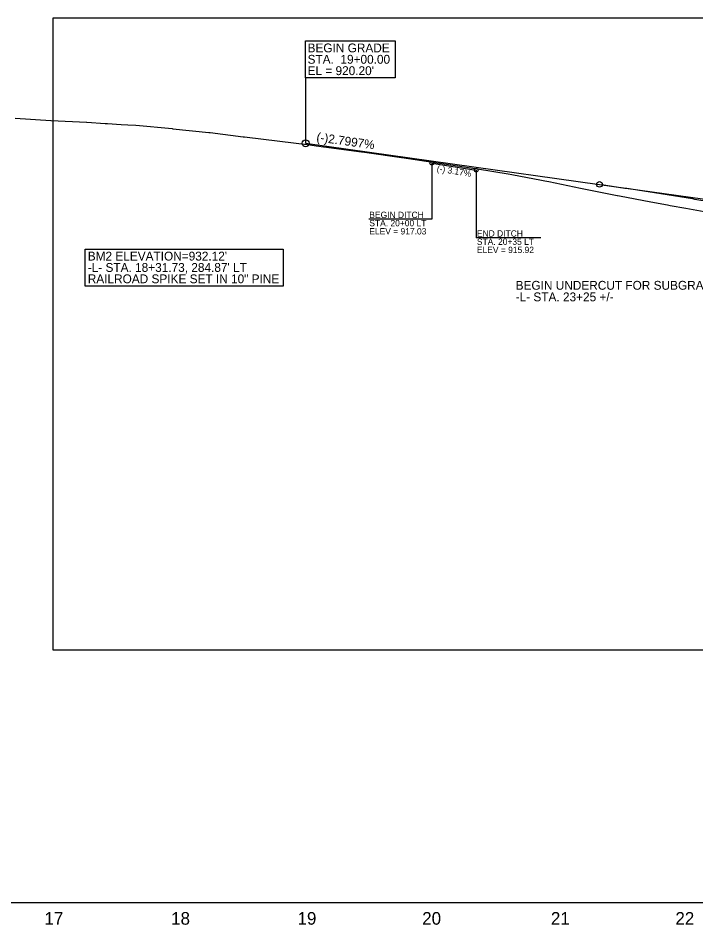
# Model space of a CAD drawing. Extents: x 1968019 to 1983409, y 545058 to 567558.
# Drawn here: x 1969515 to 1970052, y 566291 to 567008 of the extents above; entities that cross this region are included whole.
import ezdxf

# ---------------------------------------------------------------- set-up
doc = ezdxf.new("R2010")
doc.units = 0
for name, color, linetype in [('Exist Profile Cell', 7, 'Continuous'), ('Exist Vertical Profile Ground Line', 7, 'Continuous'), ('Exist Vertical Profile Horizontal Axis Label Major', 7, 'Continuous'), ('Prop Grid Mask', 7, 'Continuous'), ('Prop Road Sect_ Recs - UC (Tx)', 7, 'Continuous'), ('Prop Vertical Profile Curve Label', 7, 'Continuous'), ('Prop Vertical Profile Ditch Grade Left', 7, 'Continuous'), ('Prop Vertical Profile Ditch Grade Left Label', 7, 'Continuous'), ('Prop Vertical Profile Grade', 7, 'Continuous'), ('Prop Vertical Profile Grade Label', 7, 'Continuous'), ('Prop VPI Label', 7, 'Continuous'), ('Scratch_Level_8', 7, 'Continuous')]:
    doc.layers.add(name, color=color, linetype=linetype)

msp = doc.modelspace()

# ---------------------------------------------------------------- linework, layer by layer
at = {"layer": 'Exist Profile Cell'}
msp.add_line((1968842.96, 566308.43), (1972642.96, 566308.43), dxfattribs=at)
at = {"layer": 'Exist Vertical Profile Ground Line'}
for points in [[(1969513.03, 566929.29), (1969541.49, 566927.51), (1969541.53, 566927.51), (1969569.71, 566926.02), (1969569.88, 566926.01), (1969584.49, 566925.1), (1969584.5, 566925.1), (1969586.18, 566924.99), (1969597, 566924.28), (1969597.08, 566924.28), (1969602.31, 566924), (1969608.52, 566923.65), (1969608.62, 566923.65), (1969637.31, 566920.95), (1969638.03, 566920.89), (1969666.44, 566917.96), (1969666.98, 566917.9), (1969667.48, 566917.84), (1969693.64, 566914.53), (1969694.34, 566914.42), (1969694.67, 566914.38), (1969722.64, 566911.07), (1969722.72, 566911.06), (1969746.25, 566908.11), (1969751.44, 566907.46), (1969751.68, 566907.43), (1969757.3, 566906.68), (1969757.49, 566906.66), (1969787.15, 566902.74), (1969787.34, 566902.71), (1969788.86, 566902.49), (1969789.66, 566902.37), (1969818.88, 566898.11)], [(1969818.88, 566898.11), (1969819.01, 566898.09), (1969819.12, 566898.07), (1969849.09, 566893.57), (1969849.11, 566893.57), (1969849.17, 566893.56), (1969877.19, 566889.52), (1969879.16, 566889.2), (1969903.24, 566885.11), (1969906.31, 566884.63), (1969929.59, 566880.26), (1969932.47, 566879.73), (1969935.5, 566879.12), (1969960.47, 566873.97), (1969989.61, 566868.13), (1969989.78, 566868.1), (1969989.84, 566868.08), (1969991.42, 566867.78), (1970016.15, 566862.98), (1970029.56, 566860.62), (1970031.55, 566860.22), (1970043.92, 566858.01), (1970046.9, 566857.43), (1970058.36, 566855.38)]]:
    msp.add_lwpolyline(points, dxfattribs=at)
at = {"layer": 'Prop Grid Mask'}
msp.add_line((1969742.96, 566961.27), (1969742.96, 566909.42), dxfattribs=at)
for points in [[(1969742.96, 566990.44), (1969813.96, 566990.44), (1969813.96, 566961.27), (1969742.96, 566961.27)], [(1969568.49, 566825.54), (1969725.36, 566825.54), (1969725.36, 566796.35), (1969568.49, 566796.35)]]:
    msp.add_lwpolyline(points, close=True, dxfattribs=at)
at = {"layer": 'Prop Vertical Profile Curve Label'}
msp.add_circle((1969975.59, 566876.85), 2.25, dxfattribs=at)
at = {"layer": 'Prop Vertical Profile Ditch Grade Left'}
msp.add_line((1969842.96, 566893.58), (1969877.96, 566888.05), dxfattribs=at)
at = {"layer": 'Prop Vertical Profile Ditch Grade Left Label'}
for p, q in [((1969842.96, 566893.58), (1969842.96, 566849.28)), ((1969877.96, 566888.05), (1969877.96, 566834.56)), ((1969842.96, 566849.28), (1969793.15, 566849.28)), ((1969929.27, 566834.56), (1969877.96, 566834.56))]:
    msp.add_line(p, q, dxfattribs=at)
for centre in [(1969842.96, 566893.58), (1969877.96, 566888.05)]:
    msp.add_circle(centre, 1.5, dxfattribs=at)
at = {"layer": 'Prop Vertical Profile Grade'}
msp.add_line((1969742.96, 566909.42), (1969975.59, 566876.85), dxfattribs=at)
msp.add_spline([(1969975.59, 566876.85), (1969982.29, 566875.91), (1969988.98, 566874.95), (1969995.68, 566873.97), (1970002.37, 566872.97), (1970009.07, 566871.96), (1970015.76, 566870.94), (1970022.45, 566869.89), (1970029.15, 566868.83), (1970035.84, 566867.76), (1970042.54, 566866.66), (1970049.23, 566865.55), (1970055.93, 566864.43), (1970062.62, 566863.28), (1970069.32, 566862.12), (1970076.01, 566860.95), (1970082.71, 566859.76), (1970089.4, 566858.55), (1970096.09, 566857.32), (1970102.79, 566856.08), (1970109.48, 566854.83), (1970116.18, 566853.55), (1970122.87, 566852.26), (1970129.57, 566850.95), (1970136.26, 566849.63), (1970142.96, 566848.29), (1970149.65, 566846.93), (1970156.35, 566845.56), (1970163.04, 566844.17), (1970169.73, 566842.77), (1970176.43, 566841.35), (1970183.12, 566839.91), (1970189.82, 566838.45), (1970196.51, 566836.98), (1970203.21, 566835.49), (1970209.9, 566833.99), (1970216.6, 566832.47), (1970223.29, 566830.93), (1970229.98, 566829.38), (1970236.68, 566827.81), (1970243.37, 566826.22), (1970250.07, 566824.62), (1970256.76, 566823), (1970263.46, 566821.36), (1970270.15, 566819.71), (1970276.85, 566818.04), (1970283.54, 566816.36), (1970290.24, 566814.66), (1970296.93, 566812.94), (1970303.62, 566811.21), (1970310.32, 566809.45)], degree=3, dxfattribs=at)
at = {"layer": 'Prop VPI Label'}
msp.add_line((1969975.59, 566876.85), (1970140.23, 566853.81), dxfattribs=at)
msp.add_circle((1969742.96, 566909.42), 2.75, dxfattribs=at)
at = {"layer": 'Scratch_Level_8'}
msp.add_lwpolyline([(1969542.96, 566508.43), (1970942.96, 566508.43), (1970942.96, 566812.08), (1970792.94, 566812.08), (1970792.94, 567008.42), (1969542.96, 567008.43)], close=True, dxfattribs=at)

# ---------------------------------------------------------------- texts
at = {"layer": 'Exist Vertical Profile Horizontal Axis Label Major'}
for s, p in [('17', (1969536.38, 566290.93)), ('18', (1969636.62, 566290.93)), ('19', (1969736.66, 566290.93)), ('20', (1969835.34, 566290.93)), ('21', (1969937.18, 566290.93)), ('22', (1970035.73, 566290.93))]:
    msp.add_text(s, height=10, dxfattribs=at).set_placement(p)
at = {"layer": 'Prop Road Sect_ Recs - UC (Tx)'}
for s, p in [('BEGIN UNDERCUT FOR SUBGRADE STABILITY', (1969909.26, 566793.46)), ('-L- STA. 23+25 +/-', (1969909.26, 566784.29))]:
    msp.add_text(s, height=7, dxfattribs=at).set_placement(p)
at = {"layer": 'Prop Vertical Profile Ditch Grade Left Label'}
msp.add_text('(-) 3.17%', height=5, rotation=351.02149, dxfattribs=at).set_placement((1969846.6, 566887.07))
for s, p in [('BEGIN DITCH', (1969793.44, 566850.21)), ('STA. 20+00 LT', (1969793.44, 566843.71)), ('ELEV = 917.03', (1969793.44, 566837.21)), ('END DITCH', (1969878.59, 566835.49)), ('STA. 20+35 LT', (1969878.59, 566828.99)), ('ELEV = 915.92', (1969878.59, 566822.49))]:
    msp.add_text(s, height=5, dxfattribs=at).set_placement(p)
at = {"layer": 'Prop Vertical Profile Grade Label'}
msp.add_text('(-)2.7997%', height=7, rotation=352.03122, dxfattribs=at).set_placement((1969751.28, 566910.96))
at = {"layer": 'Prop VPI Label'}
for s, p in [('BEGIN GRADE', (1969744.57, 566981.34)), ('STA.  19+00.00', (1969744.57, 566972.34)), ("EL = 920.20'", (1969744.57, 566963.34)), ("BM2 ELEVATION=932.12'", (1969570.6, 566816.59)), ("-L- STA. 18+31.73, 284.87' LT", (1969570.6, 566807.59)), ('RAILROAD SPIKE SET IN 10" PINE', (1969570.6, 566798.59))]:
    msp.add_text(s, height=7, dxfattribs=at).set_placement(p)

doc.saveas('drawing.dxf')
